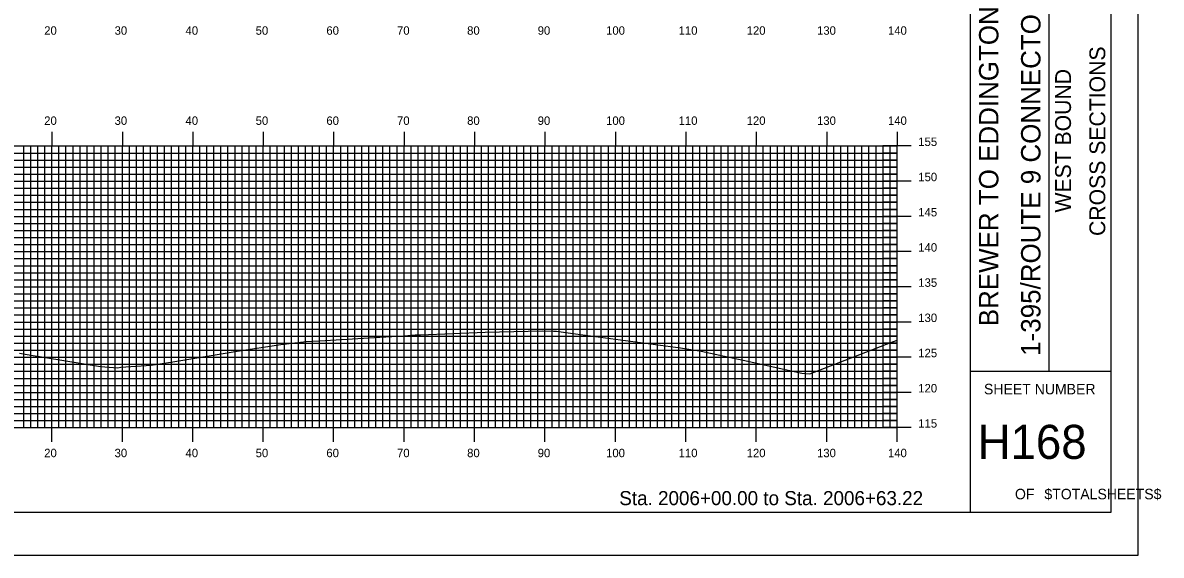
# Model space of a CAD drawing. Extents: x 852320 to 852663, y 366605 to 366825.
# Drawn here: x 852501.3 to 852663, y 366604.9 to 366680.6 of the extents above; entities that cross this region are included whole.
import ezdxf

# ---------------------------------------------------------------- set-up
doc = ezdxf.new("R2010")
doc.units = 0
for name, color, linetype in [('BORDER', 7, 'Continuous'), ('H_V ANNOTATION', 7, 'Continuous'), ('M_Roadway_Centerline', 7, 'Continuous'), ('MAJOR', 7, 'Continuous'), ('MINOR', 7, 'Continuous'), ('PLOT BOUNDARY', 7, 'Continuous'), ('S_Roadway_Centerline', 7, 'Continuous')]:
    doc.layers.add(name, color=color, linetype=linetype)

msp = doc.modelspace()

# ---------------------------------------------------------------- linework, layer by layer
at = {"layer": 'BORDER'}
for p, q in [((852635.88, 366611.06), (852635.88, 366821.06)), ((852647.06, 366631.06), (852647.06, 366701.06)), ((852635.88, 366631.06), (852655.88, 366631.06))]:
    msp.add_line(p, q, dxfattribs=at)
msp.add_lwpolyline([(852335.88, 366611.06), (852655.88, 366611.06), (852655.88, 366821.06), (852335.88, 366821.06)], close=True, dxfattribs=at)
at = {"layer": 'MAJOR'}
for p, q in [((852505.48, 366665.06), (852505.48, 366663.06)), ((852515.48, 366665.06), (852515.48, 366663.06)), ((852525.48, 366665.06), (852525.48, 366663.06)), ((852535.48, 366665.06), (852535.48, 366663.06)), ((852545.48, 366665.06), (852545.48, 366663.06)), ((852555.48, 366665.06), (852555.48, 366663.06)), ((852565.48, 366665.06), (852565.48, 366663.06)), ((852575.48, 366665.06), (852575.48, 366663.06)), ((852585.48, 366665.06), (852585.48, 366663.06)), ((852595.48, 366665.06), (852595.48, 366663.06)), ((852605.48, 366665.06), (852605.48, 366663.06)), ((852615.48, 366665.06), (852615.48, 366663.06)), ((852625.48, 366665.06), (852625.48, 366663.06)), ((852345.48, 366663.06), (852625.48, 366663.06)), ((852345.48, 366663.06), (852625.48, 366663.06)), ((852505.48, 366623.06), (852505.48, 366663.06)), ((852515.48, 366623.06), (852515.48, 366663.06)), ((852525.48, 366623.06), (852525.48, 366663.06)), ((852535.48, 366623.06), (852535.48, 366663.06)), ((852545.48, 366623.06), (852545.48, 366663.06)), ((852555.48, 366623.06), (852555.48, 366663.06)), ((852565.48, 366623.06), (852565.48, 366663.06)), ((852575.48, 366623.06), (852575.48, 366663.06)), ((852585.48, 366623.06), (852585.48, 366663.06)), ((852595.48, 366623.06), (852595.48, 366663.06)), ((852605.48, 366623.06), (852605.48, 366663.06)), ((852615.48, 366623.06), (852615.48, 366663.06)), ((852627.48, 366663.06), (852623.47, 366663.06)), ((852625.48, 366623.06), (852625.48, 366663.06)), ((852625.48, 366623.06), (852625.48, 366663.06)), ((852345.48, 366658.06), (852625.48, 366658.06)), ((852627.48, 366658.06), (852623.47, 366658.06)), ((852345.48, 366653.06), (852625.48, 366653.06)), ((852627.48, 366653.06), (852623.47, 366653.06)), ((852345.48, 366648.06), (852625.48, 366648.06)), ((852627.48, 366648.06), (852623.47, 366648.06)), ((852345.48, 366643.06), (852625.48, 366643.06)), ((852627.48, 366643.06), (852623.47, 366643.06)), ((852345.48, 366638.06), (852625.48, 366638.06)), ((852627.48, 366638.06), (852623.47, 366638.06)), ((852345.48, 366633.06), (852625.48, 366633.06)), ((852627.48, 366633.06), (852623.47, 366633.06)), ((852345.48, 366628.06), (852625.48, 366628.06)), ((852627.48, 366628.06), (852623.47, 366628.06)), ((852345.48, 366623.06), (852625.48, 366623.06)), ((852345.48, 366623.06), (852625.48, 366623.06)), ((852505.48, 366621.05), (852505.48, 366623.06)), ((852515.48, 366621.05), (852515.48, 366623.06)), ((852525.48, 366621.05), (852525.48, 366623.06)), ((852535.48, 366621.05), (852535.48, 366623.06)), ((852545.48, 366621.05), (852545.48, 366623.06)), ((852555.48, 366621.05), (852555.48, 366623.06)), ((852565.48, 366621.05), (852565.48, 366623.06)), ((852575.48, 366621.05), (852575.48, 366623.06)), ((852585.48, 366621.05), (852585.48, 366623.06)), ((852595.48, 366621.05), (852595.48, 366623.06)), ((852605.48, 366621.05), (852605.48, 366623.06)), ((852615.48, 366621.05), (852615.48, 366623.06)), ((852627.48, 366623.06), (852623.47, 366623.06)), ((852625.48, 366621.05), (852625.48, 366623.06))]:
    msp.add_line(p, q, dxfattribs=at)
at = {"layer": 'MINOR'}
for p, q in [((852501.48, 366623.06), (852501.48, 366663.06)), ((852502.48, 366623.06), (852502.48, 366663.06)), ((852503.48, 366623.06), (852503.48, 366663.06)), ((852504.48, 366623.06), (852504.48, 366663.06)), ((852506.48, 366623.06), (852506.48, 366663.06)), ((852507.48, 366623.06), (852507.48, 366663.06)), ((852508.48, 366623.06), (852508.48, 366663.06)), ((852509.48, 366623.06), (852509.48, 366663.06)), ((852510.48, 366623.06), (852510.48, 366663.06)), ((852511.48, 366623.06), (852511.48, 366663.06)), ((852512.48, 366623.06), (852512.48, 366663.06)), ((852513.48, 366623.06), (852513.48, 366663.06)), ((852514.48, 366623.06), (852514.48, 366663.06)), ((852516.48, 366623.06), (852516.48, 366663.06)), ((852517.48, 366623.06), (852517.48, 366663.06)), ((852518.48, 366623.06), (852518.48, 366663.06)), ((852519.48, 366623.06), (852519.48, 366663.06)), ((852520.48, 366623.06), (852520.48, 366663.06)), ((852521.48, 366623.06), (852521.48, 366663.06)), ((852522.48, 366623.06), (852522.48, 366663.06)), ((852523.48, 366623.06), (852523.48, 366663.06)), ((852524.48, 366623.06), (852524.48, 366663.06)), ((852526.48, 366623.06), (852526.48, 366663.06)), ((852527.48, 366623.06), (852527.48, 366663.06)), ((852528.48, 366623.06), (852528.48, 366663.06)), ((852529.48, 366623.06), (852529.48, 366663.06)), ((852530.48, 366623.06), (852530.48, 366663.06)), ((852531.48, 366623.06), (852531.48, 366663.06)), ((852532.48, 366623.06), (852532.48, 366663.06)), ((852533.48, 366623.06), (852533.48, 366663.06)), ((852534.48, 366623.06), (852534.48, 366663.06)), ((852536.48, 366623.06), (852536.48, 366663.06)), ((852537.48, 366623.06), (852537.48, 366663.06)), ((852538.48, 366623.06), (852538.48, 366663.06)), ((852539.48, 366623.06), (852539.48, 366663.06)), ((852540.48, 366623.06), (852540.48, 366663.06)), ((852541.48, 366623.06), (852541.48, 366663.06)), ((852542.48, 366623.06), (852542.48, 366663.06)), ((852543.48, 366623.06), (852543.48, 366663.06)), ((852544.48, 366623.06), (852544.48, 366663.06)), ((852546.48, 366623.06), (852546.48, 366663.06)), ((852547.48, 366623.06), (852547.48, 366663.06)), ((852548.48, 366623.06), (852548.48, 366663.06)), ((852549.48, 366623.06), (852549.48, 366663.06)), ((852550.48, 366623.06), (852550.48, 366663.06)), ((852551.48, 366623.06), (852551.48, 366663.06)), ((852552.48, 366623.06), (852552.48, 366663.06)), ((852553.48, 366623.06), (852553.48, 366663.06)), ((852554.48, 366623.06), (852554.48, 366663.06)), ((852556.48, 366623.06), (852556.48, 366663.06)), ((852557.48, 366623.06), (852557.48, 366663.06)), ((852558.48, 366623.06), (852558.48, 366663.06)), ((852559.48, 366623.06), (852559.48, 366663.06)), ((852560.48, 366623.06), (852560.48, 366663.06)), ((852561.48, 366623.06), (852561.48, 366663.06)), ((852562.48, 366623.06), (852562.48, 366663.06)), ((852563.48, 366623.06), (852563.48, 366663.06)), ((852564.48, 366623.06), (852564.48, 366663.06)), ((852566.48, 366623.06), (852566.48, 366663.06)), ((852567.48, 366623.06), (852567.48, 366663.06)), ((852568.48, 366623.06), (852568.48, 366663.06)), ((852569.48, 366623.06), (852569.48, 366663.06)), ((852570.48, 366623.06), (852570.48, 366663.06)), ((852571.48, 366623.06), (852571.48, 366663.06)), ((852572.48, 366623.06), (852572.48, 366663.06)), ((852573.48, 366623.06), (852573.48, 366663.06)), ((852574.48, 366623.06), (852574.48, 366663.06)), ((852576.48, 366623.06), (852576.48, 366663.06)), ((852577.48, 366623.06), (852577.48, 366663.06)), ((852578.48, 366623.06), (852578.48, 366663.06)), ((852579.48, 366623.06), (852579.48, 366663.06)), ((852580.48, 366623.06), (852580.48, 366663.06)), ((852581.48, 366623.06), (852581.48, 366663.06)), ((852582.48, 366623.06), (852582.48, 366663.06)), ((852583.48, 366623.06), (852583.48, 366663.06)), ((852584.48, 366623.06), (852584.48, 366663.06)), ((852586.48, 366623.06), (852586.48, 366663.06)), ((852587.48, 366623.06), (852587.48, 366663.06)), ((852588.48, 366623.06), (852588.48, 366663.06)), ((852589.48, 366623.06), (852589.48, 366663.06)), ((852590.48, 366623.06), (852590.48, 366663.06)), ((852591.48, 366623.06), (852591.48, 366663.06)), ((852592.48, 366623.06), (852592.48, 366663.06)), ((852593.48, 366623.06), (852593.48, 366663.06)), ((852594.48, 366623.06), (852594.48, 366663.06)), ((852596.48, 366623.06), (852596.48, 366663.06)), ((852597.48, 366623.06), (852597.48, 366663.06)), ((852598.48, 366623.06), (852598.48, 366663.06)), ((852599.48, 366623.06), (852599.48, 366663.06)), ((852600.48, 366623.06), (852600.48, 366663.06)), ((852601.48, 366623.06), (852601.48, 366663.06)), ((852602.48, 366623.06), (852602.48, 366663.06)), ((852603.48, 366623.06), (852603.48, 366663.06)), ((852604.48, 366623.06), (852604.48, 366663.06)), ((852606.48, 366623.06), (852606.48, 366663.06)), ((852607.48, 366623.06), (852607.48, 366663.06)), ((852608.48, 366623.06), (852608.48, 366663.06)), ((852609.48, 366623.06), (852609.48, 366663.06)), ((852610.48, 366623.06), (852610.48, 366663.06)), ((852611.48, 366623.06), (852611.48, 366663.06)), ((852612.48, 366623.06), (852612.48, 366663.06)), ((852613.48, 366623.06), (852613.48, 366663.06)), ((852614.48, 366623.06), (852614.48, 366663.06)), ((852616.48, 366623.06), (852616.48, 366663.06)), ((852617.48, 366623.06), (852617.48, 366663.06)), ((852618.48, 366623.06), (852618.48, 366663.06)), ((852619.48, 366623.06), (852619.48, 366663.06)), ((852620.48, 366623.06), (852620.48, 366663.06)), ((852621.48, 366623.06), (852621.48, 366663.06)), ((852622.48, 366623.06), (852622.48, 366663.06)), ((852623.48, 366623.06), (852623.48, 366663.06)), ((852624.48, 366623.06), (852624.48, 366663.06)), ((852345.48, 366662.06), (852625.48, 366662.06)), ((852345.48, 366661.06), (852625.48, 366661.06)), ((852625.48, 366662.06), (852623.47, 366662.06)), ((852625.48, 366661.06), (852623.47, 366661.06)), ((852345.48, 366660.06), (852625.48, 366660.06)), ((852625.48, 366660.06), (852623.47, 366660.06)), ((852345.48, 366659.06), (852625.48, 366659.06)), ((852625.48, 366659.06), (852623.47, 366659.06)), ((852345.48, 366657.06), (852625.48, 366657.06)), ((852345.48, 366656.06), (852625.48, 366656.06)), ((852625.48, 366657.06), (852623.47, 366657.06)), ((852625.48, 366656.06), (852623.47, 366656.06)), ((852345.48, 366655.06), (852625.48, 366655.06)), ((852625.48, 366655.06), (852623.47, 366655.06)), ((852345.48, 366654.06), (852625.48, 366654.06)), ((852625.48, 366654.06), (852623.47, 366654.06)), ((852345.48, 366652.06), (852625.48, 366652.06)), ((852625.48, 366652.06), (852623.47, 366652.06)), ((852345.48, 366651.06), (852625.48, 366651.06)), ((852345.48, 366650.06), (852625.48, 366650.06)), ((852625.48, 366651.06), (852623.47, 366651.06)), ((852625.48, 366650.06), (852623.47, 366650.06)), ((852345.48, 366649.06), (852625.48, 366649.06)), ((852625.48, 366649.06), (852623.47, 366649.06)), ((852345.48, 366647.06), (852625.48, 366647.06)), ((852625.48, 366647.06), (852623.47, 366647.06)), ((852345.48, 366646.06), (852625.48, 366646.06)), ((852345.48, 366645.06), (852625.48, 366645.06)), ((852625.48, 366646.06), (852623.47, 366646.06)), ((852625.48, 366645.06), (852623.47, 366645.06)), ((852345.48, 366644.06), (852625.48, 366644.06)), ((852625.48, 366644.06), (852623.47, 366644.06)), ((852345.48, 366642.06), (852625.48, 366642.06)), ((852625.48, 366642.06), (852623.47, 366642.06)), ((852345.48, 366641.06), (852625.48, 366641.06)), ((852345.48, 366640.06), (852625.48, 366640.06)), ((852625.48, 366641.06), (852623.47, 366641.06)), ((852625.48, 366640.06), (852623.47, 366640.06)), ((852345.48, 366639.06), (852625.48, 366639.06)), ((852625.48, 366639.06), (852623.47, 366639.06)), ((852345.48, 366637.06), (852625.48, 366637.06)), ((852625.48, 366637.06), (852623.47, 366637.06)), ((852345.48, 366636.06), (852625.48, 366636.06)), ((852345.48, 366635.06), (852625.48, 366635.06)), ((852625.48, 366636.06), (852623.47, 366636.06)), ((852625.48, 366635.06), (852623.47, 366635.06)), ((852345.48, 366634.06), (852625.48, 366634.06)), ((852625.48, 366634.06), (852623.47, 366634.06)), ((852345.48, 366632.06), (852625.48, 366632.06)), ((852625.48, 366632.06), (852623.47, 366632.06)), ((852345.48, 366631.06), (852625.48, 366631.06)), ((852345.48, 366630.06), (852625.48, 366630.06)), ((852625.48, 366631.06), (852623.47, 366631.06)), ((852625.48, 366630.06), (852623.47, 366630.06)), ((852345.48, 366629.06), (852625.48, 366629.06)), ((852625.48, 366629.06), (852623.47, 366629.06)), ((852345.48, 366627.06), (852625.48, 366627.06)), ((852625.48, 366627.06), (852623.47, 366627.06)), ((852345.48, 366626.06), (852625.48, 366626.06)), ((852625.48, 366626.06), (852623.47, 366626.06)), ((852345.48, 366625.06), (852625.48, 366625.06)), ((852345.48, 366624.06), (852625.48, 366624.06)), ((852625.48, 366625.06), (852623.47, 366625.06)), ((852625.48, 366624.06), (852623.47, 366624.06))]:
    msp.add_line(p, q, dxfattribs=at)
at = {"layer": 'PLOT BOUNDARY'}
msp.add_lwpolyline([(852319.69, 366604.94), (852659.69, 366604.94), (852659.69, 366824.94), (852319.69, 366824.94)], close=True, dxfattribs=at)
at = {"layer": 'S_Roadway_Centerline'}
msp.add_lwpolyline([(852500.89, 366633.65), (852501.97, 366633.46), (852512.38, 366631.73), (852514.86, 366631.56), (852515.27, 366631.64), (852519.58, 366631.95), (852522.65, 366632.42), (852531.8, 366633.9), (852537.98, 366634.85), (852541.56, 366635.31), (852544.27, 366635.45), (852552.03, 366635.93), (852555.47, 366636.12), (852557.06, 366636.22), (852557.48, 366636.25), (852557.82, 366636.25), (852566.99, 366636.61), (852575.11, 366636.83), (852576.71, 366636.78), (852577.11, 366636.74), (852579.12, 366636.48), (852594.7, 366634.41), (852597.68, 366633.93), (852603.6, 366632.62), (852611.95, 366630.8), (852613.1, 366630.72), (852624.58, 366635.15), (852625.48, 366635.47)], dxfattribs=at)

# ---------------------------------------------------------------- texts
at = {"layer": 'BORDER'}
for s, height, p in [('1-395/ROUTE 9 CONNECTOR', 2.7557, (852645.83, 366633.26)), ('BREWER TO EDDINGTON', 2.7557, (852639.86, 366637.46)), ('CROSS SECTIONS', 2.25, (852655.03, 366650.28)), ('WEST BOUND', 2.25, (852650.16, 366653.61))]:
    msp.add_text(s, height=height, rotation=90, dxfattribs=at).set_placement(p)
for s, height, p in [('SHEET NUMBER', 1.4905, (852637.81, 366627.79)), ('H168', 4.839, (852636.91, 366618.62)), ('OF', 1.491, (852642.21, 366612.88)), ('$TOTALSHEETS$', 1.4905, (852646.39, 366612.88))]:
    msp.add_text(s, height=height, dxfattribs=at).set_placement(p)
at = {"layer": 'H_V ANNOTATION'}
for s, height, p in [('20', 1.2, (852504.39, 366678.86)), ('30', 1.2, (852514.38, 366678.86)), ('40', 1.2, (852524.45, 366678.86)), ('50', 1.2, (852534.41, 366678.86)), ('60', 1.2, (852544.45, 366678.86)), ('70', 1.2, (852554.48, 366678.86)), ('80', 1.2, (852564.43, 366678.86)), ('90', 1.2, (852574.45, 366678.86)), ('100', 1.2, (852584.16, 366678.86)), ('110', 1.2, (852594.46, 366678.86)), ('120', 1.2, (852604.12, 366678.86)), ('130', 1.2, (852614.11, 366678.86)), ('140', 1.2, (852624.18, 366678.86)), ('20', 1.2, (852504.39, 366666.06)), ('30', 1.2, (852514.38, 366666.06)), ('40', 1.2, (852524.45, 366666.06)), ('50', 1.2, (852534.41, 366666.06)), ('60', 1.2, (852544.45, 366666.06)), ('70', 1.2, (852554.48, 366666.06)), ('80', 1.2, (852564.43, 366666.06)), ('90', 1.2, (852574.45, 366666.06)), ('100', 1.2, (852584.16, 366666.06)), ('110', 1.2, (852594.46, 366666.06)), ('120', 1.2, (852604.12, 366666.06)), ('130', 1.2, (852614.11, 366666.06)), ('140', 1.2, (852624.18, 366666.06)), ('155', 1.2, (852628.48, 366663.06)), ('150', 1.2, (852628.48, 366658.06)), ('145', 1.2, (852628.48, 366653.06)), ('140', 1.2, (852628.48, 366648.06)), ('135', 1.2, (852628.48, 366643.06)), ('130', 1.2, (852628.48, 366638.06)), ('125', 1.2, (852628.48, 366633.06)), ('120', 1.2, (852628.48, 366628.06)), ('115', 1.2, (852628.48, 366623.06)), ('20', 1.2, (852504.39, 366618.86)), ('30', 1.2, (852514.38, 366618.86)), ('40', 1.2, (852524.45, 366618.86)), ('50', 1.2, (852534.41, 366618.86)), ('60', 1.2, (852544.45, 366618.86)), ('70', 1.2, (852554.48, 366618.86)), ('80', 1.2, (852564.43, 366618.86)), ('90', 1.2, (852574.45, 366618.86)), ('100', 1.2, (852584.16, 366618.86)), ('110', 1.2, (852594.46, 366618.86)), ('120', 1.2, (852604.12, 366618.86)), ('130', 1.2, (852614.11, 366618.86)), ('140', 1.2, (852624.18, 366618.86)), ('Sta. 2006+00.00 to Sta. 2006+63.22', 2.0004, (852586.03, 366612.05))]:
    msp.add_text(s, height=height, dxfattribs=at).set_placement(p)
at = {"layer": 'M_Roadway_Centerline'}
for s, p in [('C', (852557.47, 366636.25)), ('L', (852557.48, 366636.24))]:
    msp.add_text(s, height=0.0146, dxfattribs=at).set_placement(p)

doc.saveas('drawing.dxf')
